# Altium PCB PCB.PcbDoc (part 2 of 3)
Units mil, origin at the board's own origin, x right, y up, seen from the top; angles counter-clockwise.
Board outline 5645.41 x 3720.47 mil, 4 copper layers (Top Layer, Signal Layer 1, Signal Layer 2, Bottom Layer), stack 61.2 mil thick; 253 components, 113 nets, 631 pads, 211 vias.
Unrouted connection lines stored in the file: 1.
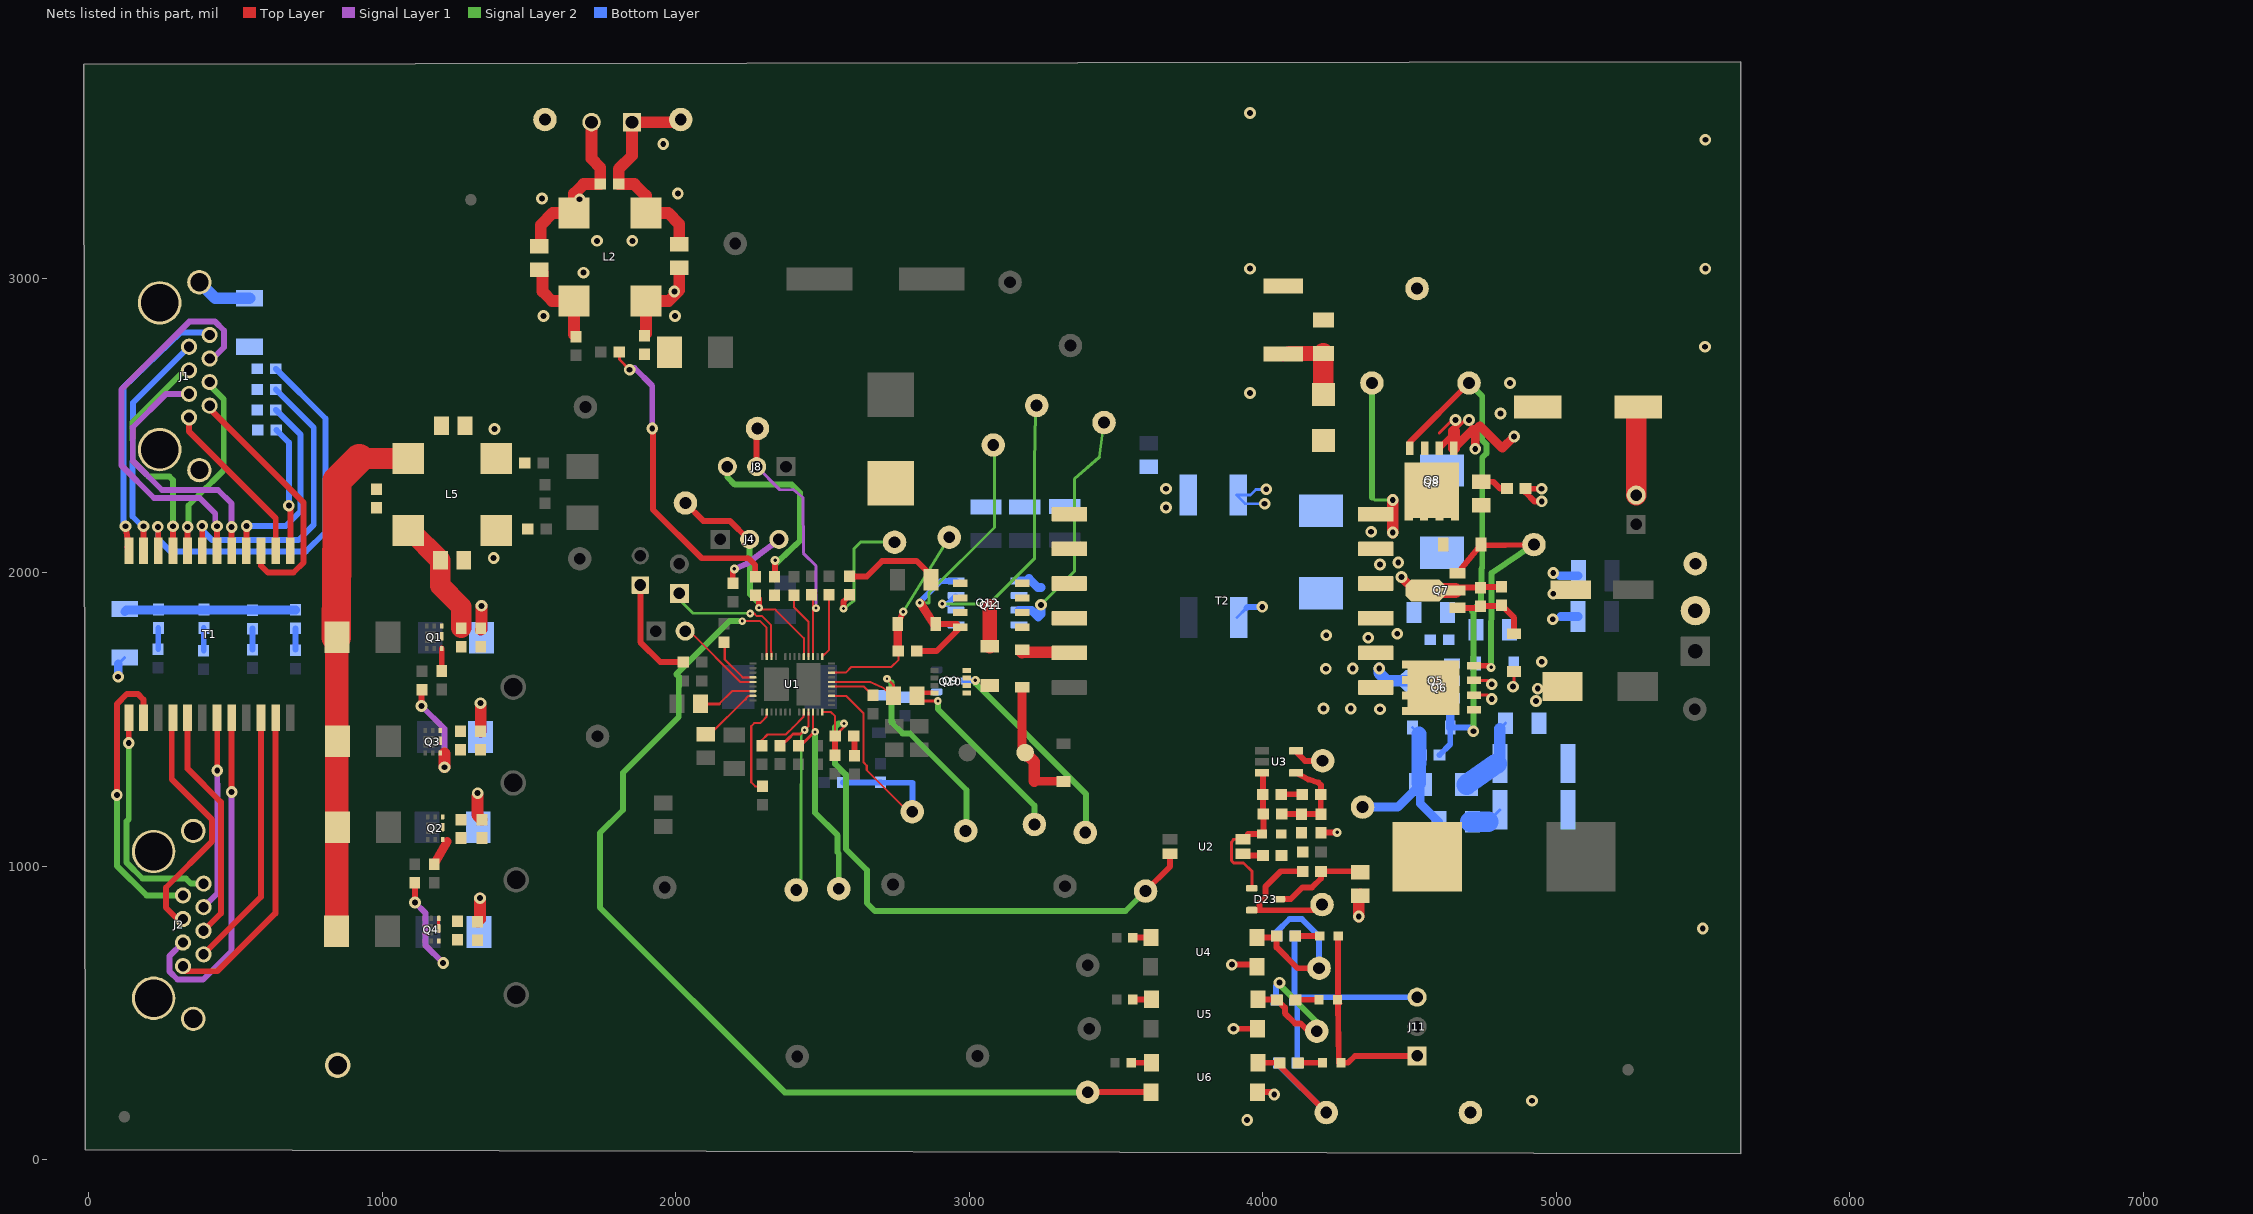
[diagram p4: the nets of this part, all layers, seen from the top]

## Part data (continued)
D11 D21: library part CMP-0005718-3, "Diode, TVS, Uni, 60 V, SMC", Manufacturer="Fairchild Semiconductor", Value1=1500W
D12 D19: library part CMP-0029196-2, "Diode, Ultrafast, 100 V, 2 A, SMA", Manufacturer="ON Semiconductor", Value1=2A, Value2=V
D13 D14 D15 D16 D20 D22: library part CMP-0076981-2, "Diode, Switching, 100 V, 0.2 A, SOD-123", Manufacturer="ON Semiconductor", Value1=0.2A, Value2=V
D17 D18: library part CMP-0005751-4, "Diode, Zener, 12 V, 500 mW, SOD-123", Manufacturer="Diodes Inc.", Power_W=500mW, Value1=0.5W
D23: library part CMP-0028456-1, "Diode, Schottky, 30 V, 0.2 A, SOT-23", Manufacturer="Diodes Inc.", Supplier Part Number 1=BAT54S-FDICT-ND, Value1=0.2A, Value2=0.65V
D24: library part CMP-0028411-2, "Diode, Schottky, 100 V, 3 A, SMC", Manufacturer="Diodes Inc.", Value1=3A, Value2=0.79V
D25 D26 D27: library part CMP-0002892-3, "LED, Yellow, SMD", Color=yellow, Manufacturer="Wurth Elektronik", Value1=W, Value2=2V
FID1 FID2 FID3: library part CMP-0077181-1, "Fiducial mark.  There is nothing to buy or mount.", Manufacturer=N/A
H1 H2 H3 H4: library part CMP-0003620-1, "Bumpon, Hemisphere, 0.44 X 0.20, Clear", Manufacturer=3M, Supplier Part Number 1=SJ5303-7-ND
J1 J2: library part CMP-0054918-1, "RJ45, No LED, tab up, R/A, TH", Color=Black, Manufacturer="TE Connectivity", Supplier Part Number 1=A97716-ND
J3: library part CMP-0055341-1, "Terminal Block, 3.5 mm, 2x1, Tin, TH", Manufacturer=Molex, Supplier Part Number 1=WM7877-ND
J4 J8 J11: library part CMP-0054951-1, "Header, 100mil, 3x1, Tin, TH", Manufacturer="TE Connectivity", Supplier Part Number 1=5-146278-3-ND
J5: library part CMP-0002337-1, "Header, 100mil, 2x1, Tin, TH", Color=Black, Current_A=3A, Manufacturer="Sullins Connector Solutions", Supplier Part Number 1=S1012E-02-ND, Voltage_V=1.8kV
J6: library part CMP-0074913-1, "Terminal Block, 3.5mm Pitch, 2x1, TH", Color=Grey, Current_A=6A, Manufacturer="On-Shore Technology", Supplier Part Number 1=ED1514-ND, Voltage_V=150V
J7 J9 J10: library part CMP-0054952-1, "Header, 100mil, 2x1, Tin, TH", Manufacturer="TE Connectivity", Supplier Part Number 1=5-146278-2-ND
L1 L3 L4 L6: library part CMP-0003192-2, "Ferrite Bead, 300 ohm @ 100 MHz, 2 A, 0603", Manufacturer="Wurth Elektronik", Supplier Part Number 1=732-1592-1-ND, Value1="0.15 ohm", Value2=2A, ValueDisplayed="300 ohm"
L2 L5: library part CMP-0013220-2, "Coupled inductor, 250 uH,  A, 0.035 ohm, SMD", Manufacturer="Wurth Elektronik", Supplier Part Number 1=732-1491-1-ND
L7: library part CMP-0063967-1, "Inductor, Shielded Drum Core, Superflux, 5.5 uH, 10 A, 0.0112 ohm, SMD", Manufacturer="Wurth Elektronik", Supplier Part Number 1=732-1171-1-ND, Value1="0.0112 ohm", Value2=10A, ValueDisplayed=5.5uH
L8: library part CMP-0064477-2, "Inductor, Shielded Drum Core, Ferrite, 15 uH, 14 A, 0.009 ohm, SMD", Manufacturer="Wurth Elektronik", Supplier Part Number 1=732-2176-1-ND, Value1="0.009 ohm", Value2=14A, ValueDisplayed=15uH
L9: library part CMP-0064865-2, "Inductor, Unshielded Drum Core, Metal Composite, 2.2 mH, 0.15 A, 6 ohm, SMD", Manufacturer="Wurth Elektronik", Supplier Part Number 1=732-3274-1-ND, Value1="6 ohm", Value2=0.15A, ValueDisplayed=2.2mH
LBL1: library part CMP-0003625-1, "Thermal Transfer Printable Labels, 0.650\" W x 0.200\" H - 10,000 per roll", Manufacturer=Brady, Supplier Part Number 1=97C5133
Logo1: library part CMP-0074844-1
Logo3: library part CMP-0074847-1, "FCC_disclaimer"
Logo4: library part CMP-0074769-1
Q1 Q2 Q3 Q4: library part CMP-0000968-2, "MOSFET, N-CH, 100 V, 4.5 A, DQK0006C (WSON-6)", Alternate Manufacturer=None, Manufacturer="Texas Instruments"
Q5 Q7: library part CMP-0000415-2, "Transistor, NPN, 100 V, 1 A, SOT-89", Manufacturer="Diodes Inc.", Supplier Part Number 1=FCX493CT-ND, Value1="1 A", Value2=300
Q6 Q8: library part CMP-0000939-2, "MOSFET, N-CH, 100 V, 90 A, PG-TDSON-8", Alternate Manufacturer=None, Manufacturer="Infineon Technologies", Supplier Part Number 1="BSC105N10LSF G-ND", Value1=0.014, Value2="40 nC"
Q8: library part CMP-0000706-1, "MOSFET, N-CH, 40 V, 100 A, DQJ0008A (VSONP-8)", Alternate Manufacturer=None, Manufacturer="Texas Instruments", Supplier Part Number 1=296-30571-1-ND, Value1=0.006, Value2="13 nC"
Q9: library part CMP-0086360-1, "MOSFET, P-CH, -80 V, -2.2 A, AEC-Q101, SOT-23", Alternate Manufacturer=None, Manufacturer=Vishay-Siliconix, Value1="? ohm", Value2="11.5 nC"
Q10: library part CMP-0000056-3, "MOSFET, P-CH, -150 V, -3 A, QFN-8", Alternate Manufacturer=None, Manufacturer="Fairchild Semiconductor", Value2="6.2 nC"
Q11: library part CMP-0001057-1, "MOSFET, N-CH, 150 V, 6.7 A, PQFN08A", Alternate Manufacturer=None, Manufacturer="Fairchild Semiconductor", Supplier Part Number 1=FDMS86250CT-ND, Value1=0.02, Value2="36 nC"
Q12: library part CMP-0001066-3, "MOSFET, N-CH, 150 V, 2.7 A, SOIC-8", Alternate Manufacturer=None, Manufacturer=Vishay-Siliconix, Supplier Part Number 1=SI4848DY-T1-E3CT-ND, Value1=0.07, Value2="17 nC"
R1: library part CMP-0022590-4, "RES, 75.0, 1%, 0.1 W, AEC-Q200 Grade 0, 0603", Manufacturer=Vishay-Dale, Power_W=100mW, Supplier Part Number 1=541-75.0HCT-ND, TempCo="100 ppm/C", Tolerance_%=1%, Value2=0.1W, Value_Code=75R0, ValueDisplayed=75.0
R2 R3 R4 R5 R6 R7 R8: library part CMP-0022590-3, "RES, 75.0, 1%, 0.1 W, 0603", Manufacturer=Vishay-Dale, Power_W=100mW, Supplier Part Number 1=541-75.0HCT-ND, TempCo="100 ppm/C", Tolerance_%=1%, Value2=0.1W, Value_Code=75R0, ValueDisplayed=75.0
R9 R12 R13 R24: library part CMP-0081857-1, "RES, 0, 0%,  W, AEC-Q200 Grade 0, 0805", Manufacturer=Rohm, Supplier Part Number 1=755-PMR10EZPJ000, Tolerance_%=0%, Value2=W, Value_Code=0
R10 R14: library part CMP-0021990-4, "RES, 100 k, 1%, 0.1 W, AEC-Q200 Grade 0, 0603", Manufacturer=Vishay-Dale, Power_W=100mW, Supplier Part Number 1=541-100KHCT-ND, TempCo="100 ppm/C", Tolerance_%=1%, Value2=0.1W, Value_Code=100k
R11: library part CMP-0022453-4, "RES, 4.42 k, 1%, 0.1 W, AEC-Q200 Grade 0, 0603", Manufacturer=Vishay-Dale, Power_W=100mW, Supplier Part Number 1=541-4.42KHCT-ND, TempCo="100 ppm/C", Tolerance_%=1%, Value2=0.1W, Value_Code=4k42, ValueDisplayed=4.42k
R15 R16 R17 R18: library part CMP-0022138-4, "RES, 1.00 M, 1%, 0.1 W, AEC-Q200 Grade 0, 0603", Manufacturer=Vishay-Dale, Power_W=100mW, Supplier Part Number 1=541-1.00MHCT-ND, TempCo="100 ppm/C", Tolerance_%=1%, Value2=0.1W, Value_Code=1M00, ValueDisplayed=1.00M
R19: library part CMP-0022066-4, "RES, 15.0 k, 1%, 0.1 W, AEC-Q200 Grade 0, 0603", Manufacturer=Vishay-Dale, Power_W=100mW, Supplier Part Number 1=541-15.0KHCT-ND, TempCo="100 ppm/C", Tolerance_%=1%, Value2=0.1W, Value_Code=15k0, ValueDisplayed=15.0k
R20 R21 R22 R23: library part CMP-0022224-4, "RES, 232 k, 1%, 0.1 W, AEC-Q200 Grade 0, 0603", Manufacturer=Vishay-Dale, Power_W=100mW, Supplier Part Number 1=541-232KHCT-ND, TempCo="100 ppm/C", Tolerance_%=1%, Value2=0.1W, Value_Code=232k
R25: library part CMP-0022008-4, "RES, 110 k, 1%, 0.1 W, AEC-Q200 Grade 0, 0603", Manufacturer=Vishay-Dale, Power_W=100mW, Supplier Part Number 1=541-110KHCT-ND, TempCo="100 ppm/C", Tolerance_%=1%, Value2=0.1W, Value_Code=110k
R26 R36 R44 R56 R57 R58 R59 R60 R61 R62 R63 R64: library part CMP-0021998-4, "RES, 10.0 k, 1%, 0.1 W, AEC-Q200 Grade 0, 0603", Manufacturer=Vishay-Dale, Power_W=100mW, Supplier Part Number 1=541-10.0KHCT-ND, TempCo="100 ppm/C", Tolerance_%=1%, Value2=0.1W, Value_Code=10k0, ValueDisplayed=10.0k
R27 R35: library part CMP-0015868-3, "RES, 10 k, 5%, 1 W, AEC-Q200 Grade 0, 2512", Manufacturer=Vishay-Dale, Power_W=1W, Supplier Part Number 1=541-10KXCT-ND, TempCo="200 ppm/C", Tolerance_%=5%, Value_Code=10k0, ValueDisplayed=10k
R28: library part CMP-0015867-3, "RES, 100, 5%, 1 W, AEC-Q200 Grade 0, 2512", Manufacturer=Vishay-Dale, Power_W=1W, Supplier Part Number 1=541-100XCT-ND, TempCo="200 ppm/C", Tolerance_%=5%, Value_Code=100R, ValueDisplayed=100
R29: library part CMP-0017020-3, "RES, 4.02 k, 1%, 0.25 W, AEC-Q200 Grade 0, 1206", Manufacturer=Vishay-Dale, Power_W=250mW, Supplier Part Number 1=541-4.02KFCT-ND, TempCo="100 ppm/C", Tolerance_%=1%, Value2=0.25W, Value_Code=4k02, ValueDisplayed=4.02k
R30: library part CMP-0022004-4, "RES, 10.0, 1%, 0.25 W, AEC-Q200 Grade 0, 0603", Manufacturer=Vishay-Dale, Power_W=250mW, Supplier Part Number 1=541-10.0SCT-ND, TempCo="100 ppm/C", Tolerance_%=1%, Value2=0.25W, Value_Code=10R0, ValueDisplayed=10.0
R31: library part CMP-0025768-4, "RES, 2.0 k, 5%, 0.1 W, AEC-Q200 Grade 0, 0603", Manufacturer=Vishay-Dale, Power_W=100mW, Supplier Part Number 1=541-2.0KGCT-ND, TempCo="200 ppm/C", Tolerance_%=5%, Value2=0.1W, Value_Code=2k00, ValueDisplayed=2.0k
R32: library part CMP-0017203-3, "RES, 8.06 k, 1%, 0.25 W, AEC-Q200 Grade 0, 1206", Manufacturer=Vishay-Dale, Power_W=250mW, Supplier Part Number 1=541-8.06KFCT-ND, TempCo="100 ppm/C", Tolerance_%=1%, Value2=0.25W, Value_Code=8k06, ValueDisplayed=8.06k
R33: library part CMP-0021833-2, "RES, 5.10, 1%, 0.125 W, AEC-Q200 Grade 0, 0805", Manufacturer=Panasonic, Power_W=125mW, Supplier Part Number 1=ERJ-6RQF5R1V-ND, TempCo="200 ppm/C", Tolerance_%=1%, Value2=0.125W, Value_Code=5R10, ValueDisplayed=5.10
R34: library part CMP-0022931-4, "RES, 237 k, 1%, 0.1 W, 0603", Manufacturer=Yageo, Power_W=100mW, Supplier Part Number 1=311-237KHRCT-ND, TempCo="100 ppm/C", Tolerance_%=1%, Value2=0.1W, Value_Code=237k
R37: library part CMP-0022532-4, "RES, 60.4 k, 1%, 0.1 W, AEC-Q200 Grade 0, 0603", Manufacturer=Vishay-Dale, Power_W=100mW, Supplier Part Number 1=541-60.4KHCT-ND, TempCo="100 ppm/C", Tolerance_%=1%, Value2=0.1W, Value_Code=60k4, ValueDisplayed=60.4k
R38: library part CMP-0022003-1, "RES, 10.0, 1%, 0.1 W, 0603", Manufacturer=Vishay-Dale, Power_W=100mW, Supplier Part Number 1=541-10.0HCT-ND, TempCo="100 ppm/C", Tolerance_%=1%, Value2=0.1W, Value_Code=10R0, ValueDisplayed=10.0
R39: library part CMP-0023143-5, "RES, 49.9, 1%, 0.1 W, 0603", Manufacturer=Yageo, Power_W=100mW, Supplier Part Number 1=311-49.9HRCT-ND, TempCo="100 ppm/C", Tolerance_%=1%, Value2=0.1W, Value_Code=49R9, ValueDisplayed=49.9
R40: library part CMP-0022447-4, "RES, 49.9 k, 1%, 0.1 W, AEC-Q200 Grade 0, 0603", Manufacturer=Vishay-Dale, Power_W=100mW, Supplier Part Number 1=541-49.9KHCT-ND, TempCo="100 ppm/C", Tolerance_%=1%, Value2=0.1W, Value_Code=49k9, ValueDisplayed=49.9k
R41 R46: library part CMP-0022268-4, "RES, 2.00 k, 1%, 0.1 W, AEC-Q200 Grade 0, 0603", Manufacturer=Vishay-Dale, Power_W=100mW, Supplier Part Number 1=541-2.00KHCT-ND, TempCo="100 ppm/C", Tolerance_%=1%, Value2=0.1W, Value_Code=2k00, ValueDisplayed=2.00k
R42: library part CMP-0023345-2, "RES, 2.00 k, 1%, 0.1 W, 0603", Manufacturer="Vishay Foil Resistors", Power_W=100mW, Supplier Part Number 1=Y16362K00000F9R-ND, TempCo="0.2 ppm/C", Tolerance_%=1%, Value2=0.1W, Value_Code=2k00, ValueDisplayed=2.00k
R43: library part CMP-0022446-5, "RES, 499, 1%, 0.1 W, AEC-Q200 Grade 0, 0603", Manufacturer=Vishay-Dale, Power_W=100mW, Supplier Part Number 1=541-499HCT-ND, TempCo="100 ppm/C", Tolerance_%=1%, Value2=0.1W, Value_Code=499R, ValueDisplayed=499
R45: library part CMP-0022410-4, "RES, 40.2 k, 1%, 0.1 W, AEC-Q200 Grade 0, 0603", Manufacturer=Vishay-Dale, Power_W=100mW, Supplier Part Number 1=541-40.2KHCT-ND, TempCo="100 ppm/C", Tolerance_%=1%, Value2=0.1W, Value_Code=40k2, ValueDisplayed=40.2k
R47: library part CMP-0021169-3, "RES, 31.6, 1%, 0.125 W, AEC-Q200 Grade 0, 0805", Manufacturer=Vishay-Dale, Power_W=125mW, Supplier Part Number 1=541-31.6CCT-ND, TempCo="100 ppm/C", Tolerance_%=1%, Value2=0.125W, Value_Code=31R6, ValueDisplayed=31.6
R48: library part CMP-0022109-1, "RES, 1.00 k, 1%, 0.1 W, 0603", Manufacturer=Vishay-Dale, Power_W=100mW, Supplier Part Number 1=541-1.00KHCT-ND, TempCo="100 ppm/C", Tolerance_%=1%, Value2=0.1W, Value_Code=1k00, ValueDisplayed=1.00k
R49: library part CMP-0020868-3, "RES, 121, 1%, 0.125 W, AEC-Q200 Grade 0, 0805", Manufacturer=Vishay-Dale, Power_W=125mW, Supplier Part Number 1=541-121CCT-ND, TempCo="100 ppm/C", Tolerance_%=1%, Value2=0.125W, Value_Code=121R, ValueDisplayed=121
R50: library part CMP-0023091-5, "RES, 3.00 k, 1%, 0.1 W, 0603", Manufacturer=Yageo, Power_W=100mW, Supplier Part Number 1=311-3.00KHRCT-ND, TempCo="100 ppm/C", Tolerance_%=1%, Value2=0.1W, Value_Code=3k00, ValueDisplayed=3.00k
R51: library part CMP-0022965-5, "RES, 27.4 k, 1%, 0.1 W, 0603", Manufacturer=Yageo, Power_W=100mW, Supplier Part Number 1=311-27.4KHRCT-ND, TempCo="100 ppm/C", Tolerance_%=1%, Value2=0.1W, Value_Code=27k4, ValueDisplayed=27.4k
R52: library part CMP-0017281-2, "RES, 0.05, 1%, 1 W, AEC-Q200 Grade 0, 1206", Manufacturer=Panasonic, Power_W=1W, Supplier Part Number 1=P0.05BVCT-ND, TempCo="50 ppm/C", Tolerance_%=1%, Value_Code=R050, ValueDisplayed=0.05
R53: library part CMP-0022000-4, "RES, 10.5 k, 1%, 0.1 W, AEC-Q200 Grade 0, 0603", Manufacturer=Vishay-Dale, Power_W=100mW, Supplier Part Number 1=541-10.5KHCT-ND, TempCo="100 ppm/C", Tolerance_%=1%, Value2=0.1W, Value_Code=10k5, ValueDisplayed=10.5k
R54: library part CMP-0022418-4, "RES, 42.2 k, 1%, 0.1 W, AEC-Q200 Grade 0, 0603", Manufacturer=Vishay-Dale, Power_W=100mW, Supplier Part Number 1=541-42.2KHCT-ND, TempCo="100 ppm/C", Tolerance_%=1%, Value2=0.1W, Value_Code=42k2, ValueDisplayed=42.2k
R55: library part CMP-0022445-4, "RES, 499 k, 1%, 0.1 W, AEC-Q200 Grade 0, 0603", Manufacturer=Vishay-Dale, Power_W=100mW, Supplier Part Number 1=541-499KHCT-ND, TempCo="100 ppm/C", Tolerance_%=1%, Value2=0.1W, Value_Code=499k
SH-J1 SH-J2 SH-J3 SH-J4 SH-J5 SH-J6 SH-J7: library part CMP-0003761-2, "Shunt, 2.54mm, Gold, Black", Manufacturer="Wurth Elektronik", Supplier Part Number 1=732-2678-ND
T1: library part CMP-0030597-1, "Transformer, 350 uH, SMT", Manufacturer="Wurth Elektronik", ValueDisplayed=350uH
T2: library part CMP-0087896-1, "Power Over Ethernet (PoE) For Configurable (For DC/DC) SMPS Transformer 1500Vrms Isolation Surface Mount", Manufacturer="Wurth Electronics"
TP1 TP2 TP3 TP4: library part CMP-0055147-1, "Test Point, Multipurpose, Red, TH", Color=Red, Manufacturer=Keystone, PartNumber=5010, Supplier Part Number 1=36-5010-ND
TP5: library part CMP-0055148-1, "Test Point, Multipurpose, Black, TH", Color=Black, Manufacturer=Keystone, PartNumber=5011, Supplier Part Number 1=36-5011-ND
TP6 TP9 TP12 TP13 TP14 TP15 TP16 TP17 TP21 TP23 TP24 TP27 TP28 TP30 TP31 TP32 TP36: library part CMP-0055137-1, "Test Point, Miniature, Red, TH", Color=Red, Manufacturer=Keystone, PartNumber=5000, Supplier Part Number 1=36-5000-ND
TP7 TP10 TP22 TP25 TP26 TP33 TP37 TP41: library part CMP-0055139-1, "Test Point, Miniature, White, TH", Color=White, Manufacturer=Keystone, PartNumber=5002, Supplier Part Number 1=36-5002-ND
TP8 TP11 TP18 TP19 TP20 TP29 TP35 TP38 TP39 TP40 TP42: library part CMP-0055138-1, "Test Point, Miniature, Black, TH", Color=Black, Manufacturer=Keystone, PartNumber=5001, Supplier Part Number 1=36-5001-ND
TP34 TP43 TP44 TP45 TP46 TP47 TP48: library part CMP-0055140-1, "Test Point, Miniature, Orange, TH", Color=Orange, Manufacturer=Keystone, PartNumber=5003, Supplier Part Number 1=36-5003-ND
U1: library part CMP-0860918-1, "TPS23730RMT, RMT0045A (VQFN-45)", Alternate Manufacturer="Texas Instruments"
U2: library part CMP-0006166-3, "Optocoupler, 3.75 kV, 80-160% CTR, SMT", Manufacturer=Vishay-Semiconductor, Supplier Part Number 1=TCMT1107CT-ND, Voltage_Isolation_Vrms=3.75kV
U3: library part CMP-0032888-1, "Adjustable Precision Shunt Regulator, 34 ppm / degC, 100 mA, -40 to 85 degC, 5-pin SOT-23 (DBV), Green (RoHS & no Sb/Br)", Manufacturer="Texas Instruments", Rating=Military, Temp Coeff(Max)(ppm/ degree C)=92, Temp Coeff(Typ)(ppm/ degree C)=34
U3: library part CMP-0032918-1, "Low Voltage Adjustable Precision Shunt Regulator, 39 ppm / degC, 15 mA, -40 to 85 degC, 5-pin SOT-23 (DBV), Green (RoHS & no Sb/Br)", Manufacturer="Texas Instruments", Rating=Catalog, Temp Coeff(Max)(ppm/ degree C)=129, Temp Coeff(Typ)(ppm/ degree C)=39
U4 U5 U6: library part CMP-0006165-3, "Optocoupler, 5 kV, 300-600% CTR, SMT", Manufacturer="Fairchild Semiconductor", Supplier Part Number 1=FOD817DS-ND, Voltage_Isolation_Vrms=5kV
ZZ1: library part CMP-0003616-3
ZZ2: library part CMP-0077236-1
ZZ3: library part CMP-0077237-1
ZZ4: library part CMP-0077238-1

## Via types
v1: diameter 40, hole 20, Top Layer to Bottom Layer, 113 vias
v2: diameter 40, hole 20, Top Layer to Bottom Layer, tented both sides, 29 vias
v3: diameter 40, hole 20, Top Layer to Bottom Layer, tented top, 15 vias
v4: diameter 19.68, hole 7.87, Top Layer to Bottom Layer, 13 vias
v5: diameter 26, hole 10, Top Layer to Bottom Layer, tented both sides, 11 vias
v6: diameter 40, hole 20, Top Layer to Bottom Layer, tented bottom, 10 vias
v7: diameter 30, hole 12, Top Layer to Bottom Layer, tented both sides, 6 vias
v8: diameter 30, hole 12, Top Layer to Bottom Layer, tented top, 5 vias
v9: diameter 26, hole 10, Top Layer to Bottom Layer, tented top, 3 vias
v10: diameter 26, hole 8, Top Layer to Bottom Layer, tented both sides, 2 vias
v11: diameter 20, hole 8, Top Layer to Bottom Layer, 1 vias
v12: diameter 26, hole 8, Top Layer to Bottom Layer, tented bottom, 1 vias
v13: diameter 26, hole 10, Top Layer to Bottom Layer, 1 vias
v14: diameter 30, hole 12, Top Layer to Bottom Layer, 1 vias

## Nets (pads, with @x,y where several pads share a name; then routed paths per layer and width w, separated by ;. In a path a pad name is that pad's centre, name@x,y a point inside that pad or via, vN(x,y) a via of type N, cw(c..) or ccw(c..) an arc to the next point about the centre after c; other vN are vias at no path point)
APD: J4.2 R10.1 TP7.1 U1.5 | length 818.4
  Top Layer w7: R10.1@2272.29,1922.46 R10.1@2284.28,1910.47 ; v9@2284.28,1873.61 2284.49,1873.4 2339.85,1873.4 2436.9,1776.35 U1.5@2436.9,1713.66
  Top Layer w20: TP7.1@2033.74,2236.79 2094.46,2176.06 2184.99,2176.06 J4.2@2248.81,2112.24 ; v9(2284.28,1879.92) R10.1@2284.28,1910.47
  Signal Layer 1 w10: J4.2@2248.81,2112.24 J4.2@2250.94,2110.12
  Signal Layer 2 w20: J4.2@2252.24,2112.84 2253.54,1925.97 2284.28,1895.23 v9(2284.28,1879.92)
BT: TP48.1 U1.12 U6.2 | length 3539.8
  Top Layer w7: v5(2227.13,1834.19) 2288.21,1834.19 2310.48,1811.93 2310.48,1714.1 U1.12@2310.91,1713.66
  Top Layer w10: TP48.1@3404.21,228.91 TP48.1@3404.85,229.56
  Top Layer w20: TP48.1@3404.85,229.56 U6.2@3620.53,229.56
  Signal Layer 2 w20: v5(2227.13,1834.19) 2183.37,1834.19 2002.68,1653.5 2011.56,1644.61 2011.56,1612.36 2010.68,1611.48 2010.68,1507.49 1820.87,1317.68 1820.87,1190.94 1742.13,1112.2 1742.13,858.93 2372.14,228.91 TP48.1@3404.21,228.91
COMP: C44.1 R46.1 TP37.1 U1.35 U2.4 | length 2068
  Top Layer w7: U1.35@2499.89,1524.69 2528.74,1524.69 2543.68,1509.75 C44.1@2543.68,1442.85
  Top Layer w10: C44.1@2543.68,1442.85 2574.06,1473.23 v5(2574.06,1485.61)
  Top Layer w20: R46.1@2543.68,1377.08 C44.1@2543.68,1442.85 ; TP37.1@3601.32,914.63 3684.55,997.86 U2.4@3684.55,1041.15
  Signal Layer 2 w20: v5(2574.06,1485.61) 2555.73,1485.61 2543.68,1473.56 2543.68,1347.71 2580.09,1311.3 2580.09,1058.26 2651.6,986.75 2651.6,873.94 2679.03,846.51 3533.2,846.51 TP37.1@3601.32,914.63
CS: C46.1 R50.1 TP25.1 U1.1 | length 645.6
  Top Layer w7: U1.1@2499.89,1713.66 2522,1735.77 2522,1922.85 C46.1@2523.35,1924.19
  Top Layer w10: R50.1@2592.97,1923.67 R50.1@2593.87,1922.76
  Top Layer w20: v9(2572.22,1876.96) 2572.22,1901.11 R50.1@2593.87,1922.76
  Signal Layer 2 w10: v9(2572.22,1876.96) 2608.27,1903.81 2608.27,2081.16 2630.38,2103.27 TP25.1@2746.06,2103.27
EARTH: C5.1 C6.1 J1.9 J1.10 J1.11 J1.12 J2.9 J2.10 J2.11 J2.12 TP5.1 | length 268
  Bottom Layer w10: C5.1@100.91,1688.29 C5.1@123.15,1710.53
  Bottom Layer w30: v2(100.91,1645) C5.1@100.91,1688.29
  Bottom Layer w40: J1.10@377.56,2988.88 431.86,2934.58 C6.1@548.29,2934.58
GND: C16.1 C17.1 C18.1 C27.1 C28.2 C29.1 C30.2 C36.1 C37.1 C47.2 D11.2 D17.2 D18.2 D21.2 J6.2 Q6.1 Q6.2 Q6.3 Q8.1 Q8.2 Q8.3 R27.2 R28.2 R32.1 R35.2 R53.2 TP18.1 TP19.1 TP20.1 TP40.1 U3.5 U4.3 U5.3 U6.3 | length 2123.7
  Top Layer w10: v1(3895.18,663.94) 3964.94,666.09 3971.15,666.28 3980.44,666.57 U4.3@3984.26,666.69 ; v1@4031.97,229.56 v1(4039.77,221.75) ; v8@4253.06,1113.84 v8(4253.89,1114.67) ; 4601.77,2474.92 4637.58,2510.73 4646.53,2519.68 v2(4656.93,2519.68) ; 4651.77,2481.17 4680.45,2509.84 4690.29,2519.68 v3(4703.13,2519.68) ; Q6.2@4720.48,1582.21 4767.16,1582.21 v2(4780.64,1568.73) ; Q6.3@4720.48,1632.21 4767.61,1632.21 v2(4780.64,1619.18) ; v1(4852.98,1611.11) 4857.07,1615.19 D17.2@4857.07,1662.62 ; v3@4938.67,2242.38 v3(4951.19,2242.38)
  Top Layer w20: v1(3895.18,663.94) 3962.79,663.94 3964.94,666.09 3968.14,669.29 3971.15,666.28 U4.3@3980.75,656.69 ; v1(3901.1,445.54) U5.3@3982.73,445.54 ; U6.3@3982.73,229.56 v1@4031.97,229.56 ; U3.5@4110.2,1392.37 4144.3,1358.27 TP18.1@4204.5,1358.27 ; R53.2@4198.17,1113.84 v8@4253.06,1113.84 ; Q8.2@4601.77,2423.18 4644.1,2465.51 4656.93,2478.34 v2(4656.93,2519.68) ; v3@4938.67,2242.38 4925.88,2242.38 4895.67,2272.59 C36.1@4895.67,2285.39 v3(4950.79,2285.39)
  Top Layer w30: Q8.1@4651.77,2423.18 4715.92,2487.33 4714.34,2485.75 4724.41,2475.67 v2(4724.41,2421.26) 4724.41,2463.99 4714.34,2474.07 4740.27,2500 4817.08,2423.18 v1(4857.07,2463.16)
  Top Layer w40: v1(4327.68,827.97) 4327.68,899.39 C47.2@4332.51,904.23 ; Q8.1@4651.77,2423.18 4651.77,2481.17
  Bottom Layer w10: C16.1@3912.79,1846.6 C16.1@3944.61,1878.41 ; v1(4006.97,2234.25) 3941.15,2234.25 3938.62,2236.79 3911.03,2264.38 3958.56,2264.38 3972.06,2277.87 3977.65,2283.46 v1(4012.58,2283.46) ; v2(4988.61,1840.55) 5007.02,1840.55 5016.43,1849.96 ; v2(4990.16,1998.03) 5003.85,1998.03 5012.98,1988.9
  Bottom Layer w20: C16.1@3944.61,1878.41 3949.25,1883.05 v1(3998.73,1883.05)
  Bottom Layer w30: 5012.98,1988.9 C27.1@5074.92,1988.9 ; 5016.43,1849.96 C29.1@5074.92,1849.96
  other v1: 3947.44,135.02 4917.65,200.31 5499.52,787.4 4951.19,1695.79 4810.6,2541.9 3956.69,2611.86 4842.95,2645.64 5507.6,2769.22 3956.69,3035.15 5508.35,3035.15 5508.35,3474.41 3956.69,3565.6
  other v2: 4990.16,1927.45
  other v3: 4931.46,1562.2 4937.41,1604.33
LINEUV: R25.1 R26.2 TP12.1 U1.38 | length 900.7
  Top Layer w7: U1.38@2531.39,1579.81 2531.82,1579.37 2581.05,1579.37 2640.12,1520.29 2640.12,1353.05 2651.27,1341.9 2651.27,1326.65 TP12.1@2806.68,1171.25
  Bottom Layer w10: R26.2@2698.58,1284.56 R26.2@2698.84,1284.82
  Bottom Layer w20: R25.1@2570.01,1284.56 R26.2@2698.58,1284.56 ; R26.2@2698.84,1284.82 2806.68,1283.74 TP12.1@2806.68,1171.25
NetC1_1: C1.1 R1.1 | length 77.3
  Bottom Layer w10: C1.1@705.58,1737.34 C1.1@709.28,1733.64
  Bottom Layer w20: C1.1@705.58,1737.34 R1.1@705.58,1809.4
NetC2_1: C2.1 R2.1 | length 71.4
  Bottom Layer w20: C2.1@559.05,1737.55 R2.1@559.05,1808.95
NetC3_1: C3.1 R3.1 | length 77.6
  Bottom Layer w10: C3.1@391.73,1733.64 C3.1@392.6,1734.5
  Bottom Layer w20: C3.1@392.6,1734.5 R3.1@392.6,1810.92
NetC4_1: C4.1 R4.1 | length 72.8
  Bottom Layer w10: C4.1@236.43,1738.59 C4.1@237.6,1739.77
  Bottom Layer w20: C4.1@237.6,1739.77 R4.1@237.6,1810.92
NetC5_2: C5.2 R1.2 R2.2 R3.2 R4.2 | length 585.1
  Bottom Layer w30: C5.2@123.15,1866.04 129.5,1872.4 R1.2@705.58,1872.4
NetC6_2: C6.2 R5.2 R6.2 R7.2 R8.2
NetC7_1: C7.1 J3.1 L2.2 R9.1 TP6.1 | length 761.2
  Top Layer w40: R9.1@2012.89,3118.69 2012.89,3187.12 1975,3225.01 L2.2@1898.97,3225.01 1898.97,3284.29 1859.83,3323.43 C7.1@1806.46,3323.43 1806.46,3374.94 1851.56,3420.05 J3.1@1851.56,3534.42 TP6.1@2017.09,3534.42
  other v1: 1852.66,3129.92 2007.87,3291.03 1957.91,3460.29
NetC7_2: C7.2 J3.2 L2.3 R12.1 TP8.1 | length 597.6
  Top Layer w40: R12.1@1540.44,3108.85 1540.44,3183.52 1581.93,3225.01 L2.3@1654.09,3225.01 1654.09,3291.03 1686.5,3323.43 C7.2@1743.46,3323.43 1743.46,3379.51 1713.77,3409.2 J3.2@1713.77,3534.42
  other v1: 1732.28,3129.92 1673.23,3271.84 1545.28,3274.34
NetC8_1: C8.1 D1.2 L1.2 R10.2 | length 1079.9
  Top Layer w10: C8.1@1808.78,2750.6 1808.78,2725.62 v1(1843.46,2690.94) ; L1.2@1905.23,2742.25 L1.2@1905.23,2744.3
  Top Layer w20: v1(1920.72,2490.72) 1922.6,2488.84 1922.6,2214.91 2089.12,2048.39 2248.81,2048.39 2271.49,2025.71 2271.49,1986.25 R10.2@2272.29,1985.45
  Signal Layer 1 w10: v1@1853.92,2690.94 1854.81,2690.94 1860.28,2696.41 v1@1860.72,2696.85
  Signal Layer 1 w20: v1(1843.46,2690.94) 1853.92,2690.94 1859.83,2696.85 1860.28,2696.41 1920.72,2635.96 v1(1920.72,2490.72)
NetC9_1: C9.1 D2.1 D3.1 D4.1 D5.1 L5.2 R13.1 | length 1809.4
  Top Layer w10: D2.1@845.01,1778.46 D2.1@845.75,1779.2
  Top Layer w70: 922.31,2388.43 L5.2@1089.27,2388.43
  Top Layer w80: D5.1@845.01,777.45 D2.1@845.01,1778.46
  Top Layer w100: D2.1@844.5,1779.43 846.46,2184.56 846.46,2312.57 922.31,2388.43
NetC9_2: C9.2 C12.2 C13.2 C14.2 C15.2 D7.2 D8.2 D9.2 D10.2 L5.3 Q1.4 Q1.7 Q2.4 Q2.7 Q3.4 Q3.7 Q4.4 Q4.7 R20.1 R21.1 R22.1 R23.1 R24.1 | length 841.7
  Top Layer w10: L5.3@1058.18,2143.55 L5.3@1089.27,2143.55 L5.3@1096.26,2143.55 ; Q4.7@1192.91,787.06 Q4.4@1192.91,821.7 ; v1(1335.31,1554.82) 1335.31,1544.5 v1@1336.15,1543.66 ; v1@1336.3,1869.81 1338.58,1872.1 v1(1338.58,1886.42)
  Top Layer w40: v1@1324.82,1237.64 1324.82,1173.49 R22.1@1339.95,1158.36 ; R23.1@1325.65,810.43 1333.49,818.26 v6(1333.49,890.47) ; R21.1@1336.15,1458.56 v1@1336.15,1543.66 ; R20.1@1336.3,1804.56 1338.58,1806.84 v1(1338.58,1886.42)
  Top Layer w70: L5.3@1096.26,2143.55 R24.1@1198.86,2040.95 1198.86,1954.45 1269.83,1883.48 C12.2@1269.83,1812.28
  other v1: 1325.65,1248.34
NetC12_1: C12.1 Q1.3 R15.1 R20.2 | length 76.4
  Top Layer w20: R15.1@1203.42,1664.44 Q1.3@1203.42,1740.81
NetC13_1: C13.1 Q3.3 R16.1 R21.2 | length 353.8
  Top Layer w10: 1212.08,1383.95 1212.6,1383.43
  Top Layer w20: v2(1134.68,1545.44) R16.1@1134.68,1610.71
  Top Layer w40: v2(1212.6,1336.69) 1212.6,1383.43
  Signal Layer 1 w20: v2(1134.68,1545.44) 1212.6,1467.53 v2(1212.6,1336.69)
NetC14_1: C14.1 Q2.3 R17.1 R22.2 | length 91.4
  Top Layer w10: C14.1@1266.47,1095.36 C14.1@1269.22,1095.36
  Top Layer w30: R17.1@1177.83,1006.73 1221.97,1083.55
NetC15_1: C15.1 Q4.3 R18.1 R23.2 | length 313.7
  Top Layer w10: R18.1@1111.38,942.91 R18.1@1112.2,942.09
  Top Layer w20: v6(1112.2,875.88) R18.1@1112.2,942.09
  Signal Layer 1 w20: v6(1112.2,875.88) 1147.65,840.44 1147.65,729.85 v2(1208.2,669.29)
NetC17_2: C17.2 D12.1 R27.1 | length 270.7
  Bottom Layer w10: C17.2@4808.41,1467.99 C17.2@4827.13,1486.71
  Bottom Layer w40: R27.1@4808.41,1348.92 C17.2@4808.41,1467.99
  Bottom Layer w70: D12.1@4694.88,1277.5 R27.1@4797.6,1348.92
NetC18_2: C18.2 C22.1 C23.1 C24.1 C25.1 L7.2 T2.1 T2.2
  other v1: 3671.26,2221.65 3671.26,2285.39
NetC19_1: C19.1 R28.1 | length 116.8
  Bottom Layer w10: 4768.55,1151.57 R28.1@4808.41,1191.44
  Bottom Layer w70: C19.1@4708.11,1151.57 4768.55,1151.57
NetC19_2: C19.2 C26.2 D11.1 D12.2 D14.1 L8.1 Q5.2 Q5.4 Q6.5 Q6.6 Q6.7 Q6.8 Q6.9 R29.2 R30.2 T2.7 T2.8 T2.9 TP16.1 | length 878.4
  Top Layer w10: Q6.9@4561.45,1585.98 Q6.9@4582.68,1607.21
  Bottom Layer w10: D14.1@4510.61,1471.95 4532.82,1449.74 ; 4532.33,1349.41 4532.82,1348.92
  Bottom Layer w30: TP16.1@4340.55,1200.79 4460.69,1200.79 D12.2@4537.4,1277.5 4537.4,1213.17 C19.2@4600.4,1150.17
  Bottom Layer w40: v2(4397.39,1673.23) 4397.39,1657.49 4423.85,1631.03 Q5.4@4534.93,1631.03
  Bottom Layer w50: D12.2@4532.33,1282.57 4532.33,1349.41 ; 4532.82,1348.92 4532.82,1449.74 ; Q5.4@4534.93,1631.03 Q5.2@4637.29,1631.03
  other v1: 4399.96,1534.12 4300.42,1536.09 4207.38,1536.63 4215.58,1672.06 4307.2,1672.56 4359.77,1777.85 4216.87,1785.99
  other v2: 4458.66,1791.34
NetC26_1: C26.1 D18.1 Q5.1 R29.1 R32.2
NetC30_1: C30.1 J7.2 | length 281.1
  Top Layer w10: C30.1@5272.85,2534.82 C30.1@5279.93,2541.9
  Top Layer w70: J7.2@5272.85,2263.78 C30.1@5272.85,2534.82
NetC31_1: C31.1 D13.1 D19.2 D21.1 Q7.2 Q7.4 Q8.5 Q8.6 Q8.7 Q8.8 Q8.9@4576.77,2285.39 Q8.9@4578.76,2274.56 R31.2 R33.1 T2.10 T2.11 T2.12 TP21.1 | length 1315.8
  Top Layer w10: Q8.5@4498.03,2186.96 4498.03,2206.65 Q8.9@4576.77,2285.39 ; Q7.4@4518.55,1938.73 Q7.4@4554.3,1938.73 ; Q8.6@4550.2,2186.96 Q8.9@4576.77,2213.54 ; Q8.7@4603.35,2186.96 Q8.9@4576.77,2213.54 ; Q8.8@4655.51,2186.96 4655.51,2206.65 Q8.9@4576.77,2285.39 ; Q7.2@4656.66,1938.73 Q7.2@4666.48,1948.55 ; C31.1@4743.12,1948.55 C31.1@4745.62,1951.05 ; Q8.9@4576.77,2213.54 Q8.9@4576.77,2285.39
  Top Layer w20: Q7.2@4666.48,1948.55 C31.1@4743.12,1948.55 ; C31.1@4745.62,1951.05 R31.2@4814.54,1951.05
  Top Layer w30: v2(4472.84,1984.44) Q7.4@4518.55,1938.73
  Top Layer w40: v1(4443.34,2136.21) v3(4443.34,2246.63)
  Top Layer w50: Q7.4@4554.3,1938.73 Q7.2@4656.66,1938.73
  Signal Layer 2 w10: 4372.51,2255.97 4381.85,2246.63 v3(4443.34,2246.63)
  Signal Layer 2 w20: 4372.51,2255.97 TP21.1@4372.51,2611.86
  other v1: 4369.89,2138.88
  other v2: 4462.37,2034.16
  other v3: 4399.96,2027.56
NetC31_2: C31.2 D17.1 Q7.1 R31.1 | length 267.6
  Top Layer w10: C31.2@4737.23,1879.67 C31.2@4743.12,1885.56 ; R31.1@4812.03,1885.56 R31.1@4814.54,1888.06
  Top Layer w20: Q7.1@4664.54,1879.67 C31.2@4737.23,1879.67 ; C31.2@4743.12,1885.56 R31.1@4812.03,1885.56 ; R31.1@4814.54,1888.06 4857.07,1845.53 D17.1@4857.07,1791.56
NetC33_1: C33.1 Q11.5 Q11.6 Q11.7 Q11.8 Q12.5 Q12.6 Q12.7 Q12.8 T2.3 T2.4 TP28.1 | length 1065.2
  Top Layer w50: C33.1@3070.8,1749.14 3070.8,1884.65
  Signal Layer 2 w10: v1(3245.03,1889.76) 3359.38,2004.11 3359.38,2319.09 3443.62,2392.67 3455.53,2480.35 TP28.1@3484.8,2509.63
  Bottom Layer w30: Q12.7@3170.33,1871.58 3212.65,1871.58 3235.86,1848.37 3245.03,1857.55 v1(3245.03,1889.76) ; Q12.5@3170.33,1971.58 3196.64,1971.58 3204.12,1979.06 3234.63,1948.55 3245.56,1948.55
NetC33_2: C33.2 Q9.3 Q10.5 Q10.6 Q10.7 Q10.8 TP23.1 | length 690.3
  Signal Layer 2 w20: v8(3021.65,1632.21) 3021.65,1622.19 3398.88,1244.96 TP23.1@3398.88,1136.03
  Bottom Layer w20: Q9.3@2984.31,1630.99 2985.53,1632.21 v8(3021.65,1632.21)
NetC35_2: C35.2 TP22.1 U1.33 | length 700.3
  Top Layer w7: v5@2468.39,1452.46 U1.33@2468.39,1524.69
  Top Layer w10: C35.2@2425.61,1411.47 2427.41,1411.47 v5@2468.39,1452.46
  Signal Layer 2 w20: v5(2475.32,1457.04) 2475.32,1181.43 2552.21,1104.53 2552.21,1046.72 2556.05,1042.88 TP22.1@2556.05,922.18
NetC36_2: C36.2 R33.2 | length 96.9
  Top Layer w20: R33.2@4745.64,2309.32 4785.64,2309.32 4809.58,2285.39 C36.2@4832.68,2285.39
NetC37_2: C37.2 D19.1 R35.1 | length 285.9
  Top Layer w10: R35.1@4069.58,2724.35 R35.1@4091.29,2746.06
  Top Layer w50: R35.1@4091.29,2746.06 C37.2@4207.38,2746.06
  Top Layer w70: D19.1@4207.38,2606.99 C37.2@4207.38,2746.06
NetC39_1: C39.1 D20.2 Q9.1 Q10.4 R36.2 TP27.1 | length 705.8
  Top Layer w10: C39.1@2822.68,1580.63 2841.22,1562.09 v5(2893.7,1562.09)
  Top Layer w15: C39.1@2816.12,1580.63 C39.1@2816.12,1589.65 ; C39.1@2823.34,1589.65 Q10.4@2875.13,1589.65
  Signal Layer 2 w20: v5(2893.7,1562.09) 2893.7,1534.82 3222.52,1206 TP27.1@3222.52,1141.73
  Bottom Layer w10: Q9.1@2880.13,1593.59 Q9.1@2889.82,1593.59
NetC39_2: C39.2 TP30.1 U1.41 | length 912.5
  Top Layer w7: U1.41@2531.39,1627.05 2663.04,1627.05 2708.98,1605.84 2734.18,1580.63 C39.2@2742.68,1580.63
  Top Layer w10: v10(2720.5,1638.58) 2742.68,1616.39 C39.2@2742.68,1580.63
  Signal Layer 2 w20: v10(2720.5,1638.58) 2733.99,1625.08 2735.88,1625.08 2735.88,1496.13 2739.37,1492.63 2735.96,1489.22 2773.67,1451.51 2798.47,1451.51 2991.16,1258.82 TP30.1@2991.16,1150.17
NetC41_1: C41.1 J8.2 TP26.1 U1.3 | length 950.7
  Top Layer w7: U1.3@2468.39,1713.66 C41.1@2468.39,1919.44
  Top Layer w10: TP26.1@2270.67,2490.16 TP26.1@2276.29,2484.53 ; C41.1@2463.64,1924.19 2468.39,1919.44 C41.1@2478.53,1929.58
  Top Layer w20: J8.2@2276.29,2360.81 TP26.1@2276.29,2484.53
  Signal Layer 1 w10: J8.2@2276.29,2360.81 2355.24,2281.87 2399.38,2281.87 ; 2401.57,2282.51 2433.53,2255.3 2435.33,2065.89 2478.53,2022.69 v5(2478.53,1878.76)
NetC42_2: C42.2 U1.40 | length 153
  Top Layer w7: U1.40@2531.39,1611.3 2642.03,1611.3 C42.2@2671.97,1581.36
NetC43_1: C43.1 D23.1 R42.1 R48.1 U2.2 U3.3 | length 536.7
  Top Layer w10: U2.2@3949.9,1108.47 U2.2@3932.58,1091.15 3901.1,1091.15 3894.11,1081.17 3894.11,1018.11 3901.66,1010.56 3935.25,1010.56 3964.61,981.2 D23.1@3964.61,923.7 ; R42.1@3997.97,1108.47 R42.1@4002.75,1113.25 ; C43.1@4001.23,1178.89 C43.1@4002.75,1177.37 ; U3.3@4001.23,1309.02 U3.3@4004.5,1309.02
  Top Layer w20: U2.2@3949.9,1108.47 R42.1@3997.97,1108.47 ; C43.1@4001.23,1178.89 R48.1@4001.23,1244.3 4001.23,1309.02 4001.23,1312.32 U3.3@4005.57,1312.32 ; R42.1@4002.75,1113.25 C43.1@4002.75,1177.37
NetC43_2: C43.2 C45.1 R45.2 R53.1 U3.4 | length 338.1
  Top Layer w10: R45.2@4132.14,1177.37 R45.2@4132.68,1176.83 ; R53.1@4198.17,1176.83 R53.1@4204.04,1170.96 ; C45.1@4198.17,1243.85 C45.1@4198.62,1244.3
  Top Layer w20: C43.2@4065.75,1177.37 R45.2@4132.14,1177.37 ; U3.4@4112.04,1318.9 4155.75,1294.98 4190.62,1284.1 4198.62,1276.1 C45.1@4198.62,1244.3 ; R45.2@4132.68,1176.83 R53.1@4198.17,1176.83 C45.1@4198.17,1243.85
NetC44_2: C44.2 R43.1 | length 68.7
  Top Layer w10: C44.2@2606.67,1442.85 C44.2@2610.05,1439.47
  Top Layer w20: R43.1@2610.05,1375.57 C44.2@2610.05,1439.47
NetC45_2: C45.2 R48.2 | length 71.4
  Top Layer w20: R48.2@4064.23,1244.3 C45.2@4135.63,1244.3
NetC47_1: C47.1 D23.3 R44.1 | length 335.4
  Top Layer w20: D23.3@4050.37,887.62 4057.53,887.56 4095.77,887.29 4135.64,927.16 4168.34,927.16 4198.77,957.59 R44.1@4199.07,982.04 C47.1@4332.52,981.96
NetD13_2: D13.2 Q6.4 Q7.3 TP15.1 | length 860.5
  Top Layer w10: v7@4773.01,1682.21 v7(4778.56,1676.66)
  Top Layer w20: Q7.3@4664.54,1997.78 4742.06,2092.56 4744.12,2092.58 4914.9,2094.56 TP15.1@4924.55,2095.04 ; Q6.4@4720.48,1682.21 v7@4773.01,1682.21
  Signal Layer 2 w20: v7(4778.56,1676.66) 4780.31,1998.03 TP15.1@4924.55,2095.04
NetD14_2: D14.2 Q5.3 Q8.4 R30.1 TP17.1 | length 1836.2
  Top Layer w10: Q8.4@4501.77,2423.18 Q8.4@4501.77,2444.14
  Top Layer w20: Q8.4@4501.77,2444.14 TP17.1@4703.28,2645.64
  Signal Layer 2 w20: TP17.1@4703.28,2645.64 4748.43,2600.48 4748.43,2450.8 4762.28,2436.95 4762.28,2405.57 4748.43,2391.72 4748.43,2015.64 4745.32,2012.53 4744.71,1899.94 4713.07,1868.31 4717.95,1863.43 v6(4717.95,1459.07)
  Bottom Layer w10: Q5.3@4639.55,1566.36 Q5.3@4645.17,1571.97 ; v6@4708.15,1471.95 4717.95,1462.15 v6(4717.95,1459.07)
  Bottom Layer w20: R30.1@4602.79,1377.95 4639.55,1414.71 D14.2@4639.55,1471.95 v6@4708.15,1471.95
  Bottom Layer w30: D14.2@4639.55,1471.95 Q5.3@4639.55,1566.36
NetD15_1: D15.1 D16.1 L9.2 | length 425.2
  Top Layer w10: L9.2@3180.02,1397.12 L9.2@3184.79,1383.83
  Top Layer w30: L9.2@3180.02,1397.12 D15.1@3180.02,1598.86 ; 3222.34,1289.37 D16.1@3321.99,1288
  Top Layer w40: L9.2@3191.07,1386.08 3222.34,1354.8 3222.34,1289.37
NetD15_2: D15.2 T2.5 | length 212.9
  Top Layer w10: T2.5@3301.81,1727.8 T2.5@3318.26,1711.34
  Top Layer w40: D15.2@3180.02,1727.8 T2.5@3369.69,1729.16
NetD22_1: D22.1 R38.1 TP31.1 U1.43 | length 686.9
  Top Layer w7: U1.43@2531.39,1658.55 2569.99,1658.55 2570.34,1658.9 2579.99,1658.9 2599.06,1677.97 2735.5,1677.97 2759.24,1701.71 R38.1@2759.24,1731.98
  Top Layer w20: D22.1@2756.93,1824.04 v7(2775.59,1866.54)
  Top Layer w30: R38.1@2756.93,1734.3 D22.1@2756.93,1824.04
  Signal Layer 2 w10: v7(2775.59,1866.54) TP31.1@2920.1,2100.22
NetD22_2: D22.2 Q11.4 Q12.4 R38.2 TP32.1 | length 1206.9
  Top Layer w10: D22.2@2882.69,1820.87 D22.2@2885.87,1824.04 ; Q11.4@2959.86,1824.04 Q11.4@2970.45,1813.45
  Top Layer w20: R38.2@2822.23,1731.98 2888.98,1731.98 Q11.4@2970.45,1813.45 ; D22.2@2885.87,1824.04 Q11.4@2959.86,1824.04
  Top Layer w30: v14@2833.5,1895.91 2882.19,1821.63 D22.2@2882.69,1820.87
  Signal Layer 2 w10: v14@2827.35,1889.76 v14@2833.5,1895.91 ; v14(2832.14,1896.29) 2862.88,1896.29 2862.88,1929.97 3086.46,2153.55 3086.46,2397.89 TP32.1@3049.98,2434.38
  Bottom Layer w20: v14(2832.14,1896.29) 2832.14,1899.23 2904.49,1971.58 Q12.4@2955.77,1971.58
NetD23_2: D23.2 R39.1 R41.2 R42.2 R44.2 R45.1 TP34.1 | length 484.1
  Top Layer w20: D23.2@3963.04,849.46 4183.32,849.46 TP34.1@4202.53,868.68 ; 3990.03,849.46 3990.03,875.98 4010.28,896.24 4010.28,930.61 4061.71,982.04 R44.2@4136.08,982.04
NetD25_1: D25.1 R59.2 | length 83.5
  Top Layer w20: R59.2@4110.99,761.54 D25.1@4194.52,761.54
NetD25_2: D25.2 D26.2 D27.2 J11.1 | length 718.3
  Top Layer w10: D26.2@4257.51,546.17 D26.2@4255.54,544.2 4257.53,542.21 D26.2@4267.49,532.25
  Top Layer w20: D26.2@4257.51,544.2 4257.53,542.21 D27.2@4259.6,329.52 ; D26.2@4257.51,546.17 D25.2@4257.51,761.54 ; D27.2@4267.49,329.52 4291.22,329.52 4314.75,353.06 J11.1@4526.26,353.06
NetD26_1: D26.1 R60.2 | length 80.4
  Top Layer w20: R60.2@4112.15,544.2 D26.1@4192.55,544.2
NetD27_1: D27.1 R61.2 | length 83.2
  Top Layer w20: R61.2@4121.26,329.52 D27.1@4204.5,329.52
NetJ1_1: J1.1 T1.2 | length 575.9
  Top Layer w20: J1.1@342.52,2528.25 342.72,2528.05 342.72,2479.8 637.8,2184.72 637.8,2074.95 T1.2@637.6,2074.76
NetJ1_2: J1.2 T1.3 | length 887.5
  Top Layer w20: J1.2@412.6,2568.4 412.6,2557.71 732.84,2237.46 732.84,2034.35 698.39,1999.9 610.86,1999.9 587.6,2023.16 T1.3@587.6,2074.76
NetJ1_3: J1.3 T1.5 | length 910.9
  Top Layer w20: T1.5@487.6,2074.76 v1(487.6,2155.02)
  Signal Layer 1 w20: J1.3@342.52,2608.56 264.57,2608.56 149.98,2493.97 150.65,2493.3 150.65,2380.74 249.99,2281.4 440.94,2281.4 487.6,2234.74 v1(487.6,2155.02)
NetJ1_4: J1.4 T1.8 | length 640.5
  Top Layer w10: T1.8@329.92,2093.75 337.6,2086.07 T1.8@337.6,2074.76
  Top Layer w20: T1.8@337.6,2101.42 v1(337.6,2155.02)
  Signal Layer 2 w10: J1.4@412.6,2638.35 J1.4@412.6,2648.72
  Signal Layer 2 w20: v1(337.6,2155.02) 340.55,2157.97 340.55,2228.54 401.51,2289.51 402.09,2289.51 436.77,2324.19 436.77,2324.76 460.5,2348.49 460.5,2590.45 J1.4@412.6,2638.35
NetJ1_5: J1.5 T1.9 | length 801.4
  Top Layer w20: T1.9@287.6,2074.76 v1(287.6,2157.38)
  Signal Layer 2 w10: J1.5@326.97,2688.88 J1.5@342.52,2688.88
  Signal Layer 2 w20: v1(287.6,2157.38) 287.6,2314.57 275.25,2326.92 204.46,2326.92 150.65,2380.74 150.65,2451.52 149.98,2452.19 149.98,2511.89 J1.5@326.97,2688.88
NetJ1_6: J1.6 T1.6 | length 1345
  Top Layer w20: T1.6@437.6,2074.76 v1(437.6,2157.38)
  Signal Layer 1 w10: J1.6@412.6,2729.03 J1.6@423.26,2729.03
  Signal Layer 1 w20: J1.6@423.26,2729.03 461.84,2767.62 461.84,2824.36 431.42,2854.78 343.25,2854.78 111.76,2623.28 111.76,2365.5 223.32,2253.94 238.03,2253.94 238.45,2253.52 378.78,2253.52 431.57,2200.72 431.57,2173.25 v1@437.6,2167.22
NetJ1_7: J1.7 T1.11 | length 789.2
  Top Layer w20: T1.11@187.6,2074.76 v1(187.6,2157.38)
  Bottom Layer w20: 149.98,2377.25 149.98,2190.84 v1@185.8,2155.02 ; 151.77,2379.62 150.65,2380.74 150.65,2456.85 151.77,2457.98 151.77,2578.44 J1.7@342.52,2769.19
NetJ1_8: J1.8 T1.12 | length 937.7
  Top Layer w10: T1.12@125.98,2086.37 T1.12@137.6,2074.76
  Top Layer w20: v1(125.98,2157.38) T1.12@137.6,2086.37
  Bottom Layer w10: J1.8@412.6,2809.35 J1.8@412.6,2809.62
  Bottom Layer w20: v1(125.98,2157.38) 119.04,2157.38 119.04,2630.56 312.69,2817.33 J1.8@412.6,2817.33
NetJ2_1: J2.1 T1.23 | length 1062.3
  Top Layer w10: J2.1@321.78,641.63 J2.1@321.78,658.95
  Top Layer w20: J2.1@321.78,641.63 438.58,641.63 637.6,840.65 ; 637.6,838.28 T1.23@637.6,1484.99
NetJ2_2: J2.2 T1.22 | length 886.6
  Top Layer w20: J2.2@391.86,699.11 587.6,894.85 T1.22@587.6,1504.68
NetJ2_3: J2.3 T1.20 | length 1176.6
  Top Layer w10: T1.20@487.6,1504.68 T1.20@490.16,1502.12
  Top Layer w20: v1(487.6,1251.87) 487.6,1499.56 T1.20@490.16,1502.12
  Signal Layer 1 w20: J2.3@321.78,739.27 276.35,693.84 276.35,640.14 302.97,613.52 390.45,613.52 487.6,710.67 v1(487.6,1251.87)
NetJ2_4: J2.4 T1.17 | length 796.5
  Top Layer w20: T1.17@337.6,1504.68 337.6,1331.18 450.79,1217.99 450.79,838.35 J2.4@391.86,779.43
NetJ2_5: J2.5 T1.16 | length 844.5
  Top Layer w10: J2.5@302.36,819.58 J2.5@321.78,819.58
  Top Layer w20: T1.16@287.6,1504.68 283.46,1500.54 283.46,1295.7 421.26,1157.9 421.26,1084.54 263.78,927.06 263.78,858.17 J2.5@302.36,819.58
NetJ2_6: J2.6 T1.19 | length 667.4
  Top Layer w10: T1.19@437.6,1504.68 T1.19@440.94,1501.33
  Top Layer w20: v1(438.58,1325.06) 438.58,1498.97 T1.19@440.94,1501.33
  Signal Layer 1 w20: J2.6@391.86,859.74 439.5,907.38 439.5,1279.95 438.58,1280.87 v1(438.58,1325.06)
NetJ2_7: J2.7 T1.14 | length 984.5
  Top Layer w20: v1(96.46,1241.57) 96.46,1551.63 131.34,1586.51 167.91,1586.51 187.6,1566.83 T1.14@187.6,1504.68
  Signal Layer 2 w20: v1@96.46,1232.18 96.46,1000.69 197.24,899.9 J2.7@321.78,899.9
NetJ2_8: J2.8 T1.13 | length 797.8
  Top Layer w10: T1.13@136.81,1503.89 T1.13@137.6,1504.68
  Top Layer w20: v1(136.81,1419.19) T1.13@136.81,1503.89
  Signal Layer 2 w20: v1@136.81,1429.03 v1(136.81,1419.19) 136.81,1159.36 129.91,1152.46 129.91,1011.45 183.73,957.63 331.64,957.63 349.21,940.06 J2.8@391.86,940.06
NetJ4_3: J4.3 R11.2 | length 246.2
  Top Layer w20: R11.2@2194.88,1963.18 2194.88,2006.57 v8(2200.7,2012.38)
  Signal Layer 1 w20: v8@2206.54,2015.15 2241.95,2028.97 2326.39,2092.33 J4.3@2361.73,2118.48
  Signal Layer 2 w10: J4.3@2348.81,2105.23 J4.3@2348.81,2112.24
NetJ5_1: J5.1 R14.1 | length 348.7
  Top Layer w10: J5.1@1879.92,1934.16 J5.1@1882.93,1934.16
  Top Layer w20: J5.1@1879.92,1934.16 1879.92,1762.65 1947.67,1694.9 R14.1@2026.03,1694.9
NetJ8_3: J8.3 R34.1 | length 676.7
  Top Layer w20: R34.1@2336.27,1985.08 2338.1,1986.91 2338.88,1987.7 v8(2338.88,2040.95)
  Signal Layer 2 w10: J8.3@2176.29,2360.81 J8.3@2201.41,2360.81
  Signal Layer 2 w20: J8.3@2176.29,2360.81 2176.29,2325.1 2201.94,2299.45 2395.76,2299.45 2423.57,2271.64 2423.57,2107.95 2349.57,2038.02 2341.5,2029.95 2340.43,2040.95 v8(2338.88,2040.95)
NetJ9_1: J9.1 U1.11 | length 499
  Top Layer w7: v5@2259.53,1860.23 v5(2253.93,1860.23) 2254.16,1860.46 2267.21,1860.46 2275.43,1852.23 2293.13,1852.23 2325.35,1820.01 2325.35,1729.91 2326.23,1729.03 2326.23,1714.1 U1.11@2326.66,1713.66
  Signal Layer 2 w10: J9.1@1988.19,1932.3 2057.8,1862.69 v5@2254.16,1860.46 ; v5@2251.48,1862.69 v5(2253.93,1860.23)
NetJ10_2: J10.2 U1.18 | length 301.6
  Top Layer w7: J10.2@2047.9,1800.18 2221.03,1627.05 U1.18@2263.67,1627.05
  Top Layer w10: J10.2@2033.74,1800.18 J10.2@2047.9,1800.18
NetJ11_3: J11.3 R56.2 R57.2 R58.2 | length 860.1
  Bottom Layer w10: R57.2@4109.22,544.2 R57.2@4113.65,548.63 ; R56.2@4109.22,759.77 R56.2@4110.99,761.54 ; R57.2@4118.07,553.06 R57.2@4113.65,548.63 ; R58.2@4118.16,329.68 R58.2@4118.32,329.52 ; R57.2@4118.16,543.95 4118.32,543.95 R57.2@4113.65,548.63
  Bottom Layer w20: R57.2@4109.22,544.2 R56.2@4109.22,759.77 ; R57.2@4118.07,553.06 J11.3@4526.26,553.06 ; R58.2@4118.16,329.68 R57.2@4118.16,543.95
NetL1_1: L1.1 L2.1 R9.2 | length 326.5
  Top Layer w10: L1.1@1898.97,2813.55 L1.1@1905.23,2807.29
  Top Layer w40: L1.1@1898.97,2813.55 L2.1@1898.97,2925.01 1976.37,2925.01 2012.89,2961.53 R9.2@2012.89,3038.69
  other v1: 1998.03,2874.22 1995.89,2957.28
NetL2_4: L2.4 L3.1 R12.2 | length 319
  Top Layer w10: R12.2@1540.44,3028.85 R12.2@1546.74,3022.55 ; L3.1@1654.09,2810.67 L3.1@1661.01,2803.75
  Top Layer w40: R12.2@1546.74,3022.55 1546.74,2957.28 1579.01,2925.01 L2.4@1654.09,2925.01 L3.1@1654.09,2810.67
  other v1: 1549.81,2874.02 1686.5,3021.65
NetL4_1: L4.1 L5.1 R13.2
  other v1: 1383.26,2488.84
NetL5_4: L5.4 L6.1 R24.2
  other v1: 1380.18,2049.11
NetQ11_1: Q11.1 Q11.2 Q11.3 Q12.1 Q12.2 Q12.3 R50.2 R52.2 TP36.1 | length 1292.6
  Top Layer w20: R50.2@2592.97,1986.66 2651.44,1986.66 2703.81,2039.04 2821.35,2039.04 2868.31,1992.08 R52.2@2868.31,1951.05
  Signal Layer 2 w10: v7(2908.31,1892.93) 3061.9,1892.93 3065.07,1889.76 3223.58,2048.28 3223.58,2374.03 TP36.1@3226.38,2541.77
  Bottom Layer w10: Q12.3@2953.48,1919.29 Q12.3@2955.77,1921.58
  Bottom Layer w20: v7(2908.31,1892.93) 2927.12,1892.93 Q12.3@2953.48,1919.29
NetR5_1: R5.1 T1.10 | length 1369
  Top Layer w10: v1@236.22,2157.88 v1@237.6,2156.5
  Top Layer w20: v1(236.22,2155.51) v1@236.22,2157.88 ; T1.10@237.6,2074.76 v1@237.6,2156.5
  Bottom Layer w10: v1(236.22,2155.51) v1@237.6,2154.13
  Bottom Layer w20: v1@237.6,2154.13 237.6,2113.1 278.7,2072 740.91,2072 807.06,2138.15 807.06,2524.89 R5.1@637.8,2694.15
NetR6_1: R6.1 T1.7 | length 1014.9
  Top Layer w10: v1(387.09,2158.96) v1@387.6,2158.46
  Top Layer w20: T1.7@387.6,2074.76 v1@387.6,2158.46
  Bottom Layer w20: v1@387.09,2144.49 421.34,2110.24 715.12,2110.24 767.32,2162.44 767.32,2493.77 R6.1@637.8,2623.29
NetR7_1: R7.1 T1.4 | length 669.5
  Top Layer w10: v1@537.6,2157.57 v1(538.77,2158.74)
  Top Layer w20: T1.4@537.6,2074.76 v1@537.6,2157.57
  Bottom Layer w20: v1(538.77,2158.74) 671.91,2158.74 722.73,2209.56 722.73,2469.46 R7.1@637.8,2554.39
NetR8_1: R8.1 T1.1 | length 430.6
  Top Layer w20: v1(682.38,2227.76) 687.6,2222.54 T1.1@687.6,2074.76
  Bottom Layer w20: R8.1@639.76,2485.49 682.38,2442.88 v1(682.38,2227.76)
NetR34_2: R34.2 R37.2 U1.4 | length 228.9
  Top Layer w7: R37.2@2403.18,1922.09 2403.18,1882.41 2452.65,1832.94 U1.4@2452.65,1713.66
NetR40_2: R40.2 U1.17 | length 181.6
  Top Layer w7: 2228.71,1642.8 U1.17@2263.67,1642.8
  Top Layer w8: R40.2@2165.79,1762.65 2167.07,1761.37 2167.07,1704.44 2228.71,1642.8
  Top Layer w10: R40.2@2167.07,1771.02 R40.2@2167.59,1771.55
NetR41_1: R41.1 U2.1 | length 70.9
  Top Layer w10: U2.1@3932.58,1041.15 U2.1@3937.74,1035.99
  Top Layer w20: U2.1@3937.74,1035.99 R41.1@4001.32,1035.99
NetR47_2: R47.2 U1.21 | length 209.4
  Top Layer w7: R47.2@2112.1,1448.37 2117.3,1448.37 2240.49,1571.55 ; 2240.49,1568.2 2240.49,1571.55 ; U1.21@2263.67,1579.81 2252.1,1579.81 2251.66,1579.37 2248.3,1579.37 2240.49,1571.55
NetR49_2: R49.2 U1.20 | length 197.4
  Top Layer w7: 2149.23,1552.39 2192.39,1595.55 U1.20@2263.67,1595.55
  Top Layer w10: R49.2@2084.11,1552.39 2149.23,1552.39
NetR51_2: R51.2 U1.24 | length 317.9
  Top Layer w7: R51.2@2296.06,1271.25 2271.3,1271.25 2257.76,1284.78 2257.76,1476.53 2267.93,1486.69 2288.46,1486.69 2293.19,1491.42 2293.19,1492.03 2310.48,1509.32 2310.48,1515.79 2310.91,1516.22 U1.24@2310.91,1524.69
NetR54_2: R54.2 U1.31 | length 210.6
  Top Layer w7: R54.2@2293.68,1409.81 2293.68,1428.51 2313.14,1447.96 2375.11,1447.96 2378.63,1451.49 2378.84,1451.49 2398.65,1471.31 2398.65,1471.51 2436.46,1509.32 2436.46,1513.8 2436.9,1514.24 U1.31@2436.9,1524.69
NetR55_2: R55.2 TP41.1 U1.32 | length 728.6
  Top Layer w7: v9(2439.51,1463.38) 2453.13,1477 2453.13,1492.88 2452.65,1493.36 U1.32@2452.65,1524.69
  Top Layer w10: R55.2@2356.44,1410.49 2360.79,1410.49 2385.42,1435.12 2385.62,1435.12 2400.27,1449.77 2425.89,1449.77 v9(2439.51,1463.38)
  Signal Layer 2 w10: TP41.1@2411.26,918.39 2427.66,934.78 2427.66,1111.86 2428.14,1452.02 v9(2439.51,1463.38)
NetR56_1: R56.1 R59.1 TP43.1 U4.4 | length 590.9
  Top Layer w10: R59.1@4043.15,756.69 R59.1@4048,761.54
  Top Layer w20: U4.4@3981.73,756.69 R59.1@4043.15,756.69 ; R59.1@4048,761.54 4048,723.01 4119.23,651.78 TP43.1@4192.38,651.78
  Bottom Layer w20: R56.1@4048,761.54 4048,776.13 4091.34,819.46 4133.71,819.46 4192.38,760.79 TP43.1@4192.38,651.78
NetR57_1: R57.1 R60.1 TP45.1 U5.4 | length 528.1
  Top Layer w10: R60.1@4047.82,545.54 R60.1@4049.16,544.2 ; TP45.1@4156.09,437.27 TP45.1@4171.03,437.27
  Top Layer w20: U5.4@3983.72,545.54 R60.1@4047.82,545.54 ; R60.1@4049.16,544.2 4075.89,517.47 4075.89,498.69 4110.57,464.01 4129.35,464.01 TP45.1@4156.09,437.27
  Signal Layer 2 w20: v1(4057.84,602.55) 4057.84,591.71 4059.81,593.68 4184.81,468.68 TP45.1@4184.81,437.27
  Bottom Layer w10: v1@4046.23,590.97 v1(4057.84,602.55)
  Bottom Layer w20: R57.1@4046.23,544.2 v1@4046.23,590.97
NetR58_1: R58.1 R61.1 TP47.1 U6.4 | length 546.2
  Top Layer w10: R61.1@4058.26,318.69 R61.1@4058.26,329.52 R61.1@4058.23,329.56
  Top Layer w20: U6.4@3983.72,329.56 R61.1@4058.23,329.56 ; R61.1@4058.26,318.69 TP47.1@4216.94,160.01
  Bottom Layer w10: R58.1@4055.33,321.62 R58.1@4055.33,329.52
  Bottom Layer w20: R58.1@4055.33,321.62 TP47.1@4216.94,160.01
NetR62_1: R62.1 U4.1 | length 62
  Top Layer w10: R62.1@3557.96,755.76 R62.1@3558.88,756.69
  Top Layer w20: R62.1@3558.88,756.69 U4.1@3619.53,756.69
NetR63_1: R63.1 U5.1 | length 63.6
  Top Layer w20: R63.1@3557.96,545.54 U5.1@3621.51,545.54
NetR64_1: R64.1 U6.1 | length 68.9
  Top Layer w20: R64.1@3552.62,329.56 U6.1@3621.51,329.56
